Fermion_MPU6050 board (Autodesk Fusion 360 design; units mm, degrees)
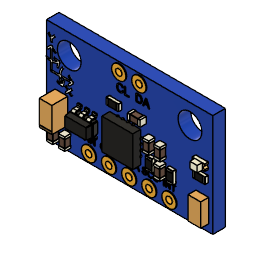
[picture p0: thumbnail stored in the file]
description: FreeCAD Model
part number: 2026-06-08-20-00-26-743
description: Part Number
part number: 2026-06-08-20-00-26-744
named bodies: "PCB"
